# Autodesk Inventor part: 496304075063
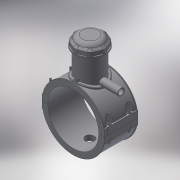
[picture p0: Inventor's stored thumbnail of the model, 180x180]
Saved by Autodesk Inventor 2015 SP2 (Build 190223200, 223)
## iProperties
Created: 2017-07
Part Number: 496304075063
Material: Generic
Description: PLASSON TAPPING SADDLE 75x63
Document SubType Name: Modeling
Designer: KIM
Mass: 852.352 g
Surface Area: 2036.61 cm^2
Volume: 852.352 cm^3
Density: 1 g/cm^3
Appearance: Default
Author: KIM
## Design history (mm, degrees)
derived "496304.ipt"
feature "Solid1::496304.ipt"
feature "Solid2::496304.ipt"
feature "Solid4::496304.ipt"
feature "Solid5::496304.ipt"
tag "TaggingFeature1"
body "Solid1"
body "Solid2"
other parameters: "d0" = 75, "d2" = 117, "d3" = 18.75, "d4" = 118, "d5" = 0, "d6" = 0.1, "d8" = 0, "d19" = 6, "d20" = 6, "d21" = 70.8, "d23" = 0, "d24" = 35.4, "d26" = 0, "d29" = 3, "d30" = 25, "d31" = 6, "d32" = 0, "d33" = 0, "d34" = 0.6, "d40" = 50.7, "d41" = 75, "d43" = 0, "d45" = 0, "d47" = 119.55, "d70" = 15, "d72" = 0, "d73" = 6, "d75" = 5, "d76" = 0, "d77" = 3.75, "d78" = 67.5, "d79" = 15, "d80" = 47.2, "d82" = 5 deg, "d84" = 4, "d85" = 14, "d86" = 0, "d87" = 3, "d88" = 0, "d89" = 1, "d90" = 1, "d91" = 94.4, "d92" = 0, "d93" = 0.5, "d94" = 39.47368, "d96" = 99.45, "d97" = 2.36, "d98" = 0, "d102" = 0.75, "d120" = 140 deg, "d121" = 24.228, "d122" = 20 deg, "d123" = 195, "d124" = 58.5, "d126" = 0, "d143" = 77.25, "d145" = 17.30769, "d149" = 1.125, "d150" = 19.03846, "d153" = 118, "d154" = 0, "d156" = 48.75, "d157" = 160 deg, "d159" = 4.5, "d161" = 1.125, "d162" = 70.8, "d163" = 0, "d164" = 37.5, "d167" = 7.5, "d168" = 47.56098, "d170" = 3.375, "d172" = 0, "d173" = 1, "d175" = 37.5, "d176" = 20 deg, "d177" = 5.25, "d178" = 22.5, "d180" = 0, "d183" = 9, "d184" = 4.2, "d185" = 38.35, "d186" = 38.35, "d187" = 48.75, "d188" = 6.75, "d189" = 5.25, "d190" = 0, "d191" = 73.125, "d193" = 6.3, "d194" = 4.13, "d195" = 90 deg, "d197" = 0, "d199" = 0, "d200" = 11.25, "d202" = 0, "d203" = 177, "d204" = 71.25, "d205" = 52.5, "d206" = 63.75, "d207" = 132.75, "d208" = 138.06, "d209" = 164.61, "d210" = 64.5, "d211" = 75, "d213" = 29.25, "d216" = 0, "d217" = 7.5, "d218" = 7.5, "d219" = 1.5, "d222" = 75, "d224" = 0, "d230" = 4.5, "d233" = 6, "d236" = 58.5, "d237" = 35.4, "d238" = 6.02433, "d240" = 35.4, "d241" = 35.4, "d242" = 35.4, "d243" = 6, "d244" = 35.4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
